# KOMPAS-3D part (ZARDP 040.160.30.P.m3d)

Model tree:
1. Булева операция:23
2. Булева операция:24
3. Булева операция:25
4. Булева операция:26
5. Булева операция:27
6. Булева операция:33
7. Булева операция:34
8. Булева операция:35
9. Булева операция:36
10. Булева операция:37
11. Булева операция:38
12. Булева операция:39
13. Булева операция:40
14. Булева операция:41
15. Булева операция:45
16. Булева операция:46
17. Булева операция:47
18. Булева операция:48
19. Булева операция:49
20. Булева операция:50
21. Булева операция:51
22. Булева операция:52
23. Булева операция:53
24. Булева операция:54
25. Булева операция:55
26. Булева операция:56

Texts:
  ООО ИК Энерпред-Ярдос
